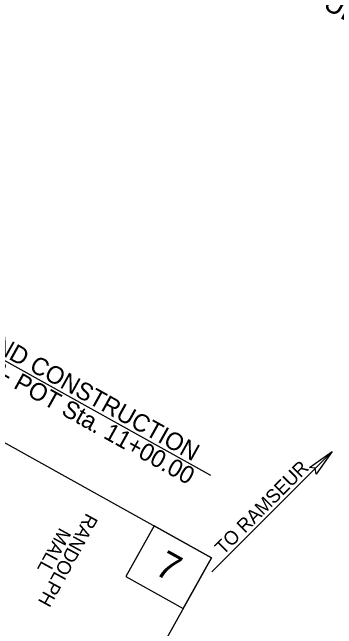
# Model space of a CAD drawing. Extents: x 1754939 to 1770240, y 706534 to 717510.
# Drawn here: x 1765886 to 1767067, y 710258 to 712504 of the extents above; entities that cross this region are included whole.
import ezdxf

# ---------------------------------------------------------------- set-up
doc = ezdxf.new("R2010")
doc.units = 0
for name, color, linetype in [('ENG SEALS CELL', 7, 'Continuous'), ('Prop Guardrail Anchor Unit CELL', 7, 'Continuous'), ('Prop SS Cut Line', 7, 'Continuous'), ('Scratch_Level_3', 7, 'Continuous'), ('Sheet PE Seal Cell', 7, 'Continuous')]:
    doc.layers.add(name, color=color, linetype=linetype)

msp = doc.modelspace()

# ---------------------------------------------------------------- linework, layer by layer
at = {"layer": 'ENG SEALS CELL'}
for points in [[(1764850.1, 710295.2), (1764850.1, 710295.2), (1765360.9, 711212.6), (1765360.9, 711212.6), (1766611.7, 710516), (1766483.1, 710285.1), (1766100.9, 709598.7)], [(1766611.7, 710516), (1766402.7, 710632.4), (1766299.8, 710447.7), (1766508.8, 710331.3)]]:
    msp.add_lwpolyline(points, close=True, dxfattribs=at)
at = {"layer": 'Prop Guardrail Anchor Unit CELL'}
msp.add_lwpolyline([(1766968.8, 710846.1), (1767050.5, 710904), (1766992.9, 710821.4), (1766989.4, 710842.7)], close=True, dxfattribs=at)
at = {"layer": 'Prop SS Cut Line'}
msp.add_line((1765759.5, 711289.8), (1766608.3, 710817.1), dxfattribs=at)
at = {"layer": 'Sheet PE Seal Cell'}
msp.add_line((1766613.2, 710465.4), (1767050.5, 710904), dxfattribs=at)

# ---------------------------------------------------------------- texts
at = {"layer": 'ENG SEALS CELL'}
msp.add_text('7', height=100, rotation=330.8875, dxfattribs=at).set_placement((1766399.9, 710460.3))
at = {"layer": 'Prop SS Cut Line'}
for s, p in [('END CONSTRUCTION', (1765766.2, 711300.1)), ('-Y8- POT Sta. 11+00.00', (1765725.5, 711227.1))]:
    msp.add_text(s, height=63.75, rotation=330.8875, dxfattribs=at).set_placement(p)
at = {"layer": 'Scratch_Level_3'}
msp.add_text('DRAINAGE, GRADING, PAVING, SIGNALS AND CULVERTS', height=75.001, rotation=330.8875, dxfattribs=at).set_placement((1764991.8, 713646.3))
at = {"layer": 'Sheet PE Seal Cell'}
for s, rotation, p in [('TO RAMSEUR', 45.0794, (1766654.3, 710524.6)), ('RANDOLPH ', 241.3314, (1766156.2, 710682.1)), ('MALL', 241.3314, (1766058.8, 710629.2))]:
    msp.add_text(s, height=50, rotation=rotation, dxfattribs=at).set_placement(p)

doc.saveas('drawing.dxf')
